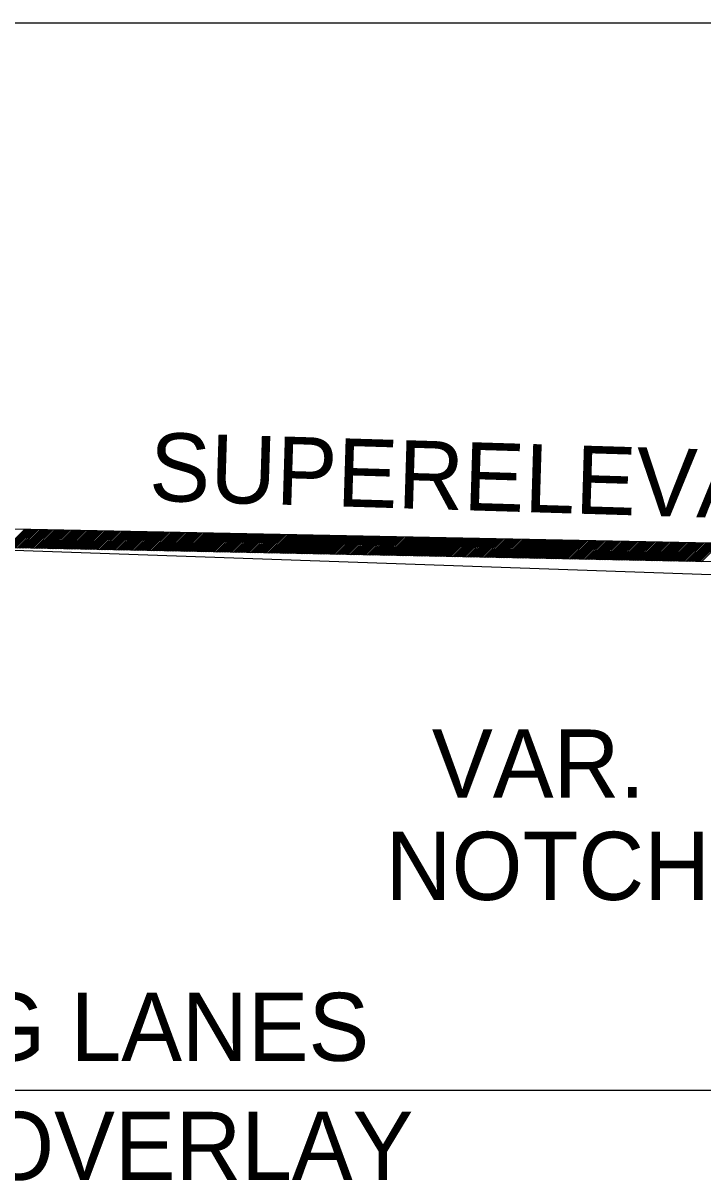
# Model space of a CAD drawing. Extents: x 2478 to 3210, y 439 to 841.
# Drawn here: x 3033.24 to 3045.19, y 774.76 to 795.13 of the extents above; entities that cross this region are included whole.
import ezdxf

# ---------------------------------------------------------------- set-up
doc = ezdxf.new("R2010")
doc.units = 0
for name, color, linetype in [('19', 7, 'Continuous'), ('R_Annotation', 7, 'Continuous'), ('R_Dimension', 7, 'Continuous'), ('R_Exist Surface', 7, 'Continuous')]:
    doc.layers.add(name, color=color, linetype=linetype)

msp = doc.modelspace()

# ---------------------------------------------------------------- linework, layer by layer
at = {"layer": '19'}
for p, q in [((3033.266, 786.223), (3032.942, 785.899)), ((3033.293, 786.222), (3032.97, 785.898)), ((3033.321, 786.222), (3032.997, 785.898)), ((3033.349, 786.221), (3033.025, 785.897)), ((3033.377, 786.22), (3033.053, 785.897)), ((3033.404, 786.22), (3033.081, 785.896)), ((3033.432, 786.219), (3033.108, 785.896)), ((3033.46, 786.219), (3033.136, 785.895)), ((3033.487, 786.218), (3033.164, 785.895)), ((3033.515, 786.218), (3033.192, 785.894)), ((3033.543, 786.217), (3033.219, 785.893)), ((3033.571, 786.217), (3033.247, 785.893)), ((3033.598, 786.216), (3033.275, 785.892)), ((3033.626, 786.215), (3033.303, 785.892)), ((3033.654, 786.215), (3033.33, 785.891)), ((3033.682, 786.214), (3033.358, 785.891)), ((3033.709, 786.214), (3033.386, 785.89)), ((3033.737, 786.213), (3033.413, 785.89)), ((3033.765, 786.213), (3033.441, 785.889)), ((3033.792, 786.212), (3033.469, 785.888)), ((3033.82, 786.212), (3033.497, 785.888)), ((3033.848, 786.211), (3033.524, 785.887)), ((3033.876, 786.21), (3033.552, 785.887)), ((3033.903, 786.21), (3033.58, 785.886)), ((3033.931, 786.209), (3033.608, 785.886)), ((3033.959, 786.209), (3033.635, 785.885)), ((3033.987, 786.208), (3033.663, 785.885)), ((3034.014, 786.208), (3033.691, 785.884)), ((3034.042, 786.207), (3033.718, 785.883)), ((3034.07, 786.207), (3033.746, 785.883)), ((3034.098, 786.206), (3033.774, 785.882)), ((3034.125, 786.205), (3033.802, 785.882)), ((3034.153, 786.205), (3033.829, 785.881)), ((3034.181, 786.204), (3033.857, 785.881)), ((3034.208, 786.204), (3033.885, 785.88)), ((3034.236, 786.203), (3033.913, 785.88)), ((3034.264, 786.203), (3033.94, 785.879)), ((3034.292, 786.202), (3033.968, 785.878)), ((3034.319, 786.202), (3033.996, 785.878)), ((3034.347, 786.201), (3034.023, 785.877)), ((3034.375, 786.2), (3034.051, 785.877)), ((3034.403, 786.2), (3034.079, 785.876)), ((3034.43, 786.199), (3034.107, 785.876)), ((3034.458, 786.199), (3034.134, 785.875)), ((3034.486, 786.198), (3034.162, 785.875)), ((3034.513, 786.198), (3034.19, 785.874)), ((3034.541, 786.197), (3034.218, 785.874)), ((3034.569, 786.197), (3034.245, 785.873)), ((3034.597, 786.196), (3034.273, 785.872)), ((3034.624, 786.195), (3034.301, 785.872)), ((3034.652, 786.195), (3034.329, 785.871)), ((3034.68, 786.194), (3034.356, 785.871)), ((3034.708, 786.194), (3034.384, 785.87)), ((3034.735, 786.193), (3034.412, 785.87)), ((3034.763, 786.193), (3034.439, 785.869)), ((3034.791, 786.192), (3034.467, 785.869)), ((3034.818, 786.192), (3034.495, 785.868)), ((3034.846, 786.191), (3034.523, 785.867)), ((3034.874, 786.19), (3034.55, 785.867)), ((3034.902, 786.19), (3034.578, 785.866)), ((3034.929, 786.189), (3034.606, 785.866)), ((3034.957, 786.189), (3034.634, 785.865)), ((3034.985, 786.188), (3034.661, 785.865)), ((3035.013, 786.188), (3034.689, 785.864)), ((3035.04, 786.187), (3034.717, 785.864)), ((3035.068, 786.187), (3034.744, 785.863)), ((3035.096, 786.186), (3034.772, 785.862)), ((3035.124, 786.185), (3034.8, 785.862)), ((3035.151, 786.185), (3034.828, 785.861)), ((3035.179, 786.184), (3034.855, 785.861)), ((3035.207, 786.184), (3034.883, 785.86)), ((3035.234, 786.183), (3034.911, 785.86)), ((3035.262, 786.183), (3034.939, 785.859)), ((3035.29, 786.182), (3034.966, 785.859)), ((3035.318, 786.182), (3034.994, 785.858)), ((3035.345, 786.181), (3035.022, 785.857)), ((3035.373, 786.18), (3035.049, 785.857)), ((3035.401, 786.18), (3035.077, 785.856)), ((3035.429, 786.179), (3035.105, 785.856)), ((3035.456, 786.179), (3035.133, 785.855)), ((3035.484, 786.178), (3035.16, 785.855)), ((3035.512, 786.178), (3035.188, 785.854)), ((3035.539, 786.177), (3035.216, 785.854)), ((3035.567, 786.177), (3035.244, 785.853)), ((3035.595, 786.176), (3035.271, 785.852)), ((3035.623, 786.175), (3035.299, 785.852)), ((3035.65, 786.175), (3035.327, 785.851)), ((3035.678, 786.174), (3035.355, 785.851)), ((3035.706, 786.174), (3035.382, 785.85)), ((3035.734, 786.173), (3035.41, 785.85)), ((3035.761, 786.173), (3035.438, 785.849)), ((3035.789, 786.172), (3035.465, 785.849)), ((3035.817, 786.172), (3035.493, 785.848)), ((3035.844, 786.171), (3035.521, 785.847)), ((3035.872, 786.17), (3035.549, 785.847)), ((3035.9, 786.17), (3035.576, 785.846)), ((3035.928, 786.169), (3035.604, 785.846)), ((3035.955, 786.169), (3035.632, 785.845)), ((3035.983, 786.168), (3035.66, 785.845)), ((3036.011, 786.168), (3035.687, 785.844)), ((3036.039, 786.167), (3035.715, 785.844)), ((3036.066, 786.167), (3035.743, 785.843)), ((3036.094, 786.166), (3035.77, 785.842)), ((3036.122, 786.165), (3035.798, 785.842)), ((3036.15, 786.165), (3035.826, 785.841)), ((3036.177, 786.164), (3035.854, 785.841)), ((3036.205, 786.164), (3035.881, 785.84)), ((3036.233, 786.163), (3035.909, 785.84)), ((3036.26, 786.163), (3035.937, 785.839)), ((3036.288, 786.162), (3035.965, 785.839)), ((3036.316, 786.162), (3035.992, 785.838)), ((3036.344, 786.161), (3036.02, 785.837)), ((3036.371, 786.16), (3036.048, 785.837)), ((3036.399, 786.16), (3036.075, 785.836)), ((3036.427, 786.159), (3036.103, 785.836)), ((3036.455, 786.159), (3036.131, 785.835)), ((3036.482, 786.158), (3036.159, 785.835)), ((3036.51, 786.158), (3036.186, 785.834)), ((3036.538, 786.157), (3036.214, 785.834)), ((3036.565, 786.157), (3036.242, 785.833)), ((3036.593, 786.156), (3036.27, 785.832)), ((3036.621, 786.156), (3036.297, 785.832)), ((3036.649, 786.155), (3036.325, 785.831)), ((3036.676, 786.154), (3036.353, 785.831)), ((3036.704, 786.154), (3036.381, 785.83)), ((3036.732, 786.153), (3036.408, 785.83)), ((3036.76, 786.153), (3036.436, 785.829)), ((3036.787, 786.152), (3036.464, 785.829)), ((3036.815, 786.152), (3036.491, 785.828)), ((3036.843, 786.151), (3036.519, 785.827)), ((3036.87, 786.151), (3036.547, 785.827)), ((3036.898, 786.15), (3036.575, 785.826)), ((3036.926, 786.149), (3036.602, 785.826)), ((3036.954, 786.149), (3036.63, 785.825)), ((3036.981, 786.148), (3036.658, 785.825)), ((3037.009, 786.148), (3036.686, 785.824)), ((3037.037, 786.147), (3036.713, 785.824)), ((3037.065, 786.147), (3036.741, 785.823)), ((3037.092, 786.146), (3036.769, 785.822)), ((3037.12, 786.146), (3036.796, 785.822)), ((3037.148, 786.145), (3036.824, 785.821)), ((3037.176, 786.144), (3036.852, 785.821)), ((3037.203, 786.144), (3036.88, 785.82)), ((3037.231, 786.143), (3036.907, 785.82)), ((3037.259, 786.143), (3036.935, 785.819)), ((3037.286, 786.142), (3036.963, 785.819)), ((3037.314, 786.142), (3036.991, 785.818)), ((3037.342, 786.141), (3037.018, 785.817)), ((3037.37, 786.141), (3037.046, 785.817)), ((3037.397, 786.14), (3037.074, 785.816)), ((3037.425, 786.139), (3037.101, 785.816)), ((3037.453, 786.139), (3037.129, 785.815)), ((3037.481, 786.138), (3037.157, 785.815)), ((3037.508, 786.138), (3037.185, 785.814)), ((3037.536, 786.137), (3037.212, 785.814)), ((3037.564, 786.137), (3037.24, 785.813)), ((3037.591, 786.136), (3037.268, 785.813)), ((3037.619, 786.136), (3037.296, 785.812)), ((3037.647, 786.135), (3037.323, 785.811)), ((3037.675, 786.134), (3037.351, 785.811)), ((3037.702, 786.134), (3037.379, 785.81)), ((3037.73, 786.133), (3037.407, 785.81)), ((3037.758, 786.133), (3037.434, 785.809)), ((3037.786, 786.132), (3037.462, 785.809)), ((3037.813, 786.132), (3037.49, 785.808)), ((3037.841, 786.131), (3037.517, 785.808)), ((3037.869, 786.131), (3037.545, 785.807)), ((3037.896, 786.13), (3037.573, 785.806)), ((3037.924, 786.129), (3037.601, 785.806)), ((3037.952, 786.129), (3037.628, 785.805)), ((3037.98, 786.128), (3037.656, 785.805)), ((3038.007, 786.128), (3037.684, 785.804)), ((3038.035, 786.127), (3037.712, 785.804)), ((3038.063, 786.127), (3037.739, 785.803)), ((3038.091, 786.126), (3037.767, 785.803)), ((3038.118, 786.126), (3037.795, 785.802)), ((3038.146, 786.125), (3037.822, 785.801)), ((3038.174, 786.124), (3037.85, 785.801)), ((3038.202, 786.124), (3037.878, 785.8)), ((3038.229, 786.123), (3037.906, 785.8)), ((3038.257, 786.123), (3037.933, 785.799)), ((3038.285, 786.122), (3037.961, 785.799)), ((3038.312, 786.122), (3037.989, 785.798)), ((3038.34, 786.121), (3038.017, 785.798)), ((3038.368, 786.121), (3038.044, 785.797)), ((3038.396, 786.12), (3038.072, 785.796)), ((3038.423, 786.119), (3038.1, 785.796)), ((3038.451, 786.119), (3038.127, 785.795)), ((3038.479, 786.118), (3038.155, 785.795)), ((3038.507, 786.118), (3038.183, 785.794)), ((3038.534, 786.117), (3038.211, 785.794)), ((3038.562, 786.117), (3038.238, 785.793)), ((3038.59, 786.116), (3038.266, 785.793)), ((3038.617, 786.116), (3038.294, 785.792)), ((3038.645, 786.115), (3038.322, 785.791)), ((3038.673, 786.114), (3038.349, 785.791)), ((3038.701, 786.114), (3038.377, 785.79)), ((3038.728, 786.113), (3038.405, 785.79)), ((3038.756, 786.113), (3038.433, 785.789)), ((3038.784, 786.112), (3038.46, 785.789)), ((3038.812, 786.112), (3038.488, 785.788)), ((3038.839, 786.111), (3038.516, 785.788)), ((3038.867, 786.111), (3038.543, 785.787)), ((3038.895, 786.11), (3038.571, 785.786)), ((3038.922, 786.109), (3038.599, 785.786)), ((3038.95, 786.109), (3038.627, 785.785)), ((3038.978, 786.108), (3038.654, 785.785)), ((3039.006, 786.108), (3038.682, 785.784)), ((3039.033, 786.107), (3038.71, 785.784)), ((3039.061, 786.107), (3038.738, 785.783)), ((3039.089, 786.106), (3038.765, 785.783)), ((3039.117, 786.106), (3038.793, 785.782)), ((3039.144, 786.105), (3038.821, 785.781)), ((3039.172, 786.104), (3038.848, 785.781)), ((3039.2, 786.104), (3038.876, 785.78)), ((3039.228, 786.103), (3038.904, 785.78)), ((3039.255, 786.103), (3038.932, 785.779)), ((3039.283, 786.102), (3038.959, 785.779)), ((3039.311, 786.102), (3038.987, 785.778)), ((3039.338, 786.101), (3039.015, 785.778)), ((3039.366, 786.101), (3039.043, 785.777)), ((3039.394, 786.1), (3039.07, 785.776)), ((3039.422, 786.099), (3039.098, 785.776)), ((3039.449, 786.099), (3039.126, 785.775)), ((3039.477, 786.098), (3039.153, 785.775)), ((3039.505, 786.098), (3039.181, 785.774)), ((3039.533, 786.097), (3039.209, 785.774)), ((3039.56, 786.097), (3039.237, 785.773)), ((3039.588, 786.096), (3039.264, 785.773)), ((3039.616, 786.096), (3039.292, 785.772)), ((3039.643, 786.095), (3039.32, 785.771)), ((3039.671, 786.095), (3039.348, 785.771)), ((3039.699, 786.094), (3039.375, 785.77)), ((3039.727, 786.093), (3039.403, 785.77)), ((3039.754, 786.093), (3039.431, 785.769)), ((3039.782, 786.092), (3039.459, 785.769)), ((3039.81, 786.092), (3039.486, 785.768)), ((3039.838, 786.091), (3039.514, 785.768)), ((3039.865, 786.091), (3039.542, 785.767)), ((3039.893, 786.09), (3039.569, 785.766)), ((3039.921, 786.09), (3039.597, 785.766)), ((3039.948, 786.089), (3039.625, 785.765)), ((3039.976, 786.088), (3039.653, 785.765)), ((3040.004, 786.088), (3039.68, 785.764)), ((3040.032, 786.087), (3039.708, 785.764)), ((3040.059, 786.087), (3039.736, 785.763)), ((3040.087, 786.086), (3039.764, 785.763)), ((3040.115, 786.086), (3039.791, 785.762)), ((3040.143, 786.085), (3039.819, 785.761)), ((3040.17, 786.085), (3039.847, 785.761)), ((3040.198, 786.084), (3039.874, 785.76)), ((3040.226, 786.083), (3039.902, 785.76)), ((3040.254, 786.083), (3039.93, 785.759)), ((3040.281, 786.082), (3039.958, 785.759)), ((3040.309, 786.082), (3039.985, 785.758)), ((3040.337, 786.081), (3040.013, 785.758)), ((3040.364, 786.081), (3040.041, 785.757)), ((3040.392, 786.08), (3040.069, 785.756)), ((3040.42, 786.08), (3040.096, 785.756)), ((3040.448, 786.079), (3040.124, 785.755)), ((3040.475, 786.078), (3040.152, 785.755)), ((3040.503, 786.078), (3040.179, 785.754)), ((3040.531, 786.077), (3040.207, 785.754)), ((3040.559, 786.077), (3040.235, 785.753)), ((3040.586, 786.076), (3040.263, 785.753)), ((3040.614, 786.076), (3040.29, 785.752)), ((3040.642, 786.075), (3040.318, 785.751)), ((3040.669, 786.075), (3040.346, 785.751)), ((3040.697, 786.074), (3040.374, 785.75)), ((3040.725, 786.073), (3040.401, 785.75)), ((3040.753, 786.073), (3040.429, 785.749)), ((3040.78, 786.072), (3040.457, 785.749)), ((3040.808, 786.072), (3040.484, 785.748)), ((3040.836, 786.071), (3040.512, 785.748)), ((3040.864, 786.071), (3040.54, 785.747)), ((3040.891, 786.07), (3040.568, 785.747)), ((3040.919, 786.07), (3040.595, 785.746)), ((3040.947, 786.069), (3040.623, 785.745)), ((3040.974, 786.068), (3040.651, 785.745)), ((3041.002, 786.068), (3040.679, 785.744)), ((3041.03, 786.067), (3040.706, 785.744)), ((3041.058, 786.067), (3040.734, 785.743)), ((3041.085, 786.066), (3040.762, 785.743)), ((3041.113, 786.066), (3040.79, 785.742)), ((3041.141, 786.065), (3040.817, 785.742)), ((3041.169, 786.065), (3040.845, 785.741)), ((3041.196, 786.064), (3040.873, 785.74)), ((3041.224, 786.063), (3040.9, 785.74)), ((3041.252, 786.063), (3040.928, 785.739)), ((3041.279, 786.062), (3040.956, 785.739)), ((3041.307, 786.062), (3040.984, 785.738)), ((3041.335, 786.061), (3041.011, 785.738)), ((3041.363, 786.061), (3041.039, 785.737)), ((3041.39, 786.06), (3041.067, 785.737)), ((3041.418, 786.06), (3041.095, 785.736)), ((3041.446, 786.059), (3041.122, 785.735)), ((3041.474, 786.058), (3041.15, 785.735)), ((3041.501, 786.058), (3041.178, 785.734)), ((3041.529, 786.057), (3041.205, 785.734)), ((3041.557, 786.057), (3041.233, 785.733)), ((3041.585, 786.056), (3041.261, 785.733)), ((3041.612, 786.056), (3041.289, 785.732)), ((3041.64, 786.055), (3041.316, 785.732)), ((3041.668, 786.055), (3041.344, 785.731)), ((3041.695, 786.054), (3041.372, 785.73)), ((3041.723, 786.053), (3041.4, 785.73)), ((3041.751, 786.053), (3041.427, 785.729)), ((3041.779, 786.052), (3041.455, 785.729)), ((3041.806, 786.052), (3041.483, 785.728)), ((3041.834, 786.051), (3041.51, 785.728)), ((3041.862, 786.051), (3041.538, 785.727)), ((3041.89, 786.05), (3041.566, 785.727)), ((3041.917, 786.05), (3041.594, 785.726)), ((3041.945, 786.049), (3041.621, 785.725)), ((3041.973, 786.048), (3041.649, 785.725)), ((3042, 786.048), (3041.677, 785.724)), ((3042.028, 786.047), (3041.705, 785.724)), ((3042.056, 786.047), (3041.732, 785.723)), ((3042.084, 786.046), (3041.76, 785.723)), ((3042.111, 786.046), (3041.788, 785.722)), ((3042.139, 786.045), (3041.816, 785.722)), ((3042.167, 786.045), (3041.843, 785.721)), ((3042.195, 786.044), (3041.871, 785.72)), ((3042.222, 786.043), (3041.899, 785.72)), ((3042.25, 786.043), (3041.926, 785.719)), ((3042.278, 786.042), (3041.954, 785.719)), ((3042.305, 786.042), (3041.982, 785.718)), ((3042.333, 786.041), (3042.01, 785.718)), ((3042.361, 786.041), (3042.037, 785.717)), ((3042.389, 786.04), (3042.065, 785.717)), ((3042.416, 786.04), (3042.093, 785.716)), ((3042.444, 786.039), (3042.121, 785.715)), ((3042.472, 786.038), (3042.148, 785.715)), ((3042.5, 786.038), (3042.176, 785.714)), ((3042.527, 786.037), (3042.204, 785.714)), ((3042.555, 786.037), (3042.231, 785.713)), ((3042.583, 786.036), (3042.259, 785.713)), ((3042.611, 786.036), (3042.287, 785.712)), ((3042.638, 786.035), (3042.315, 785.712)), ((3042.666, 786.035), (3042.342, 785.711)), ((3042.694, 786.034), (3042.37, 785.71)), ((3042.721, 786.033), (3042.398, 785.71)), ((3042.749, 786.033), (3042.426, 785.709)), ((3042.777, 786.032), (3042.453, 785.709)), ((3042.805, 786.032), (3042.481, 785.708)), ((3042.832, 786.031), (3042.509, 785.708)), ((3042.86, 786.031), (3042.536, 785.707)), ((3042.888, 786.03), (3042.564, 785.707)), ((3042.916, 786.03), (3042.592, 785.706)), ((3042.943, 786.029), (3042.62, 785.705)), ((3042.971, 786.029), (3042.647, 785.705)), ((3042.999, 786.028), (3042.675, 785.704)), ((3043.026, 786.027), (3042.703, 785.704)), ((3043.054, 786.027), (3042.731, 785.703)), ((3043.082, 786.026), (3042.758, 785.703)), ((3043.11, 786.026), (3042.786, 785.702)), ((3043.137, 786.025), (3042.814, 785.702)), ((3043.165, 786.025), (3042.842, 785.701)), ((3043.193, 786.024), (3042.869, 785.7)), ((3043.221, 786.024), (3042.897, 785.7)), ((3043.248, 786.023), (3042.925, 785.699)), ((3043.276, 786.022), (3042.952, 785.699)), ((3043.304, 786.022), (3042.98, 785.698)), ((3043.331, 786.021), (3043.008, 785.698)), ((3043.359, 786.021), (3043.036, 785.697)), ((3043.387, 786.02), (3043.063, 785.697)), ((3043.415, 786.02), (3043.091, 785.696)), ((3043.442, 786.019), (3043.119, 785.695)), ((3043.47, 786.019), (3043.147, 785.695)), ((3043.498, 786.018), (3043.174, 785.694)), ((3043.526, 786.017), (3043.202, 785.694)), ((3043.553, 786.017), (3043.23, 785.693)), ((3043.581, 786.016), (3043.257, 785.693)), ((3043.609, 786.016), (3043.285, 785.692)), ((3043.637, 786.015), (3043.313, 785.692)), ((3043.664, 786.015), (3043.341, 785.691)), ((3043.692, 786.014), (3043.368, 785.69)), ((3043.72, 786.014), (3043.396, 785.69)), ((3043.747, 786.013), (3043.424, 785.689)), ((3043.775, 786.012), (3043.452, 785.689)), ((3043.803, 786.012), (3043.479, 785.688)), ((3043.831, 786.011), (3043.507, 785.688)), ((3043.858, 786.011), (3043.535, 785.687)), ((3043.886, 786.01), (3043.562, 785.687)), ((3043.914, 786.01), (3043.59, 785.686)), ((3043.942, 786.009), (3043.618, 785.686)), ((3043.969, 786.009), (3043.646, 785.685)), ((3043.997, 786.008), (3043.673, 785.684)), ((3044.025, 786.007), (3043.701, 785.684)), ((3044.052, 786.007), (3043.729, 785.683)), ((3044.08, 786.006), (3043.757, 785.683)), ((3044.108, 786.006), (3043.784, 785.682)), ((3044.136, 786.005), (3043.812, 785.682)), ((3044.163, 786.005), (3043.84, 785.681)), ((3044.191, 786.004), (3043.868, 785.681)), ((3044.219, 786.004), (3043.895, 785.68)), ((3044.247, 786.003), (3043.923, 785.679)), ((3044.274, 786.002), (3043.951, 785.679)), ((3044.302, 786.002), (3043.978, 785.678)), ((3044.33, 786.001), (3044.006, 785.678)), ((3044.357, 786.001), (3044.034, 785.677)), ((3044.385, 786), (3044.062, 785.677)), ((3044.413, 786), (3044.089, 785.676)), ((3044.441, 785.999), (3044.117, 785.676)), ((3044.468, 785.999), (3044.145, 785.675)), ((3044.496, 785.998), (3044.173, 785.674)), ((3044.524, 785.997), (3044.2, 785.674)), ((3044.552, 785.997), (3044.228, 785.673)), ((3044.579, 785.996), (3044.256, 785.673)), ((3044.607, 785.996), (3044.283, 785.672)), ((3044.635, 785.995), (3044.311, 785.672)), ((3044.663, 785.995), (3044.339, 785.671)), ((3044.69, 785.994), (3044.367, 785.671)), ((3044.718, 785.994), (3044.394, 785.67)), ((3044.746, 785.993), (3044.422, 785.669)), ((3044.773, 785.992), (3044.45, 785.669)), ((3044.801, 785.992), (3044.478, 785.668)), ((3044.829, 785.991), (3044.505, 785.668)), ((3044.857, 785.991), (3044.533, 785.667)), ((3044.884, 785.99), (3044.561, 785.667)), ((3044.912, 785.99), (3044.588, 785.666)), ((3044.94, 785.989), (3044.616, 785.666)), ((3044.968, 785.989), (3044.644, 785.665)), ((3044.995, 785.988), (3044.672, 785.664)), ((3045.023, 785.987), (3044.699, 785.664)), ((3045.051, 785.987), (3044.727, 785.663)), ((3045.078, 785.986), (3044.755, 785.663)), ((3045.106, 785.986), (3044.783, 785.662)), ((3045.134, 785.985), (3044.81, 785.662)), ((3045.162, 785.985), (3044.838, 785.661)), ((3045.189, 785.984), (3044.866, 785.661)), ((3045.217, 785.984), (3044.894, 785.66)), ((3045.245, 785.983), (3044.921, 785.659)), ((3045.273, 785.982), (3044.949, 785.659)), ((3045.3, 785.982), (3044.977, 785.658)), ((3045.328, 785.981), (3045.004, 785.658)), ((3045.356, 785.981), (3045.032, 785.657)), ((3045.383, 785.98), (3045.06, 785.657)), ((3045.411, 785.98), (3045.088, 785.656)), ((3045.439, 785.979), (3045.115, 785.656)), ((3045.467, 785.979), (3045.143, 785.655)), ((3045.494, 785.978), (3045.171, 785.654))]:
    msp.add_line(p, q, dxfattribs=at)
at = {"layer": 'R_Annotation'}
for p, q in [((3053.233, 785.823), (3031.233, 786.263)), ((3053.227, 785.493), (3031.227, 785.933))]:
    msp.add_line(p, q, dxfattribs=at)
at = {"layer": 'R_Dimension'}
for p, q in [((3070.657, 795.13), (2989.723, 795.13)), ((3011.233, 776.355), (3051.233, 776.355))]:
    msp.add_line(p, q, dxfattribs=at)
at = {"layer": 'R_Exist Surface'}
msp.add_lwpolyline([(2974.394, 779.542), (2980.464, 779.356), (2991.6, 780.578), (3008.322, 785.91), (3009.233, 786.036), (3031.233, 785.919), (3053.233, 785.156), (3055.82, 784.789), (3076.957, 782.83), (3083.428, 781.714), (3088.64, 782.82)], dxfattribs=at)

# ---------------------------------------------------------------- texts
at = {"layer": 'R_Annotation'}
msp.add_text('SUPERELEVATION', height=1.2, rotation=358.2609, dxfattribs=at).set_placement((3035.448, 786.729))
for s, height, p in [('VAR.', 1.2, (3040.43, 781.502)), ('NOTCH', 1.2, (3039.617, 779.702)), ('20\'-0" EXISTING LANES', 1.197, (3021.64, 776.872)), ('RETAIN AND OVERLAY', 1.197, (3022.403, 774.778))]:
    msp.add_text(s, height=height, dxfattribs=at).set_placement(p)

doc.saveas('drawing.dxf')
